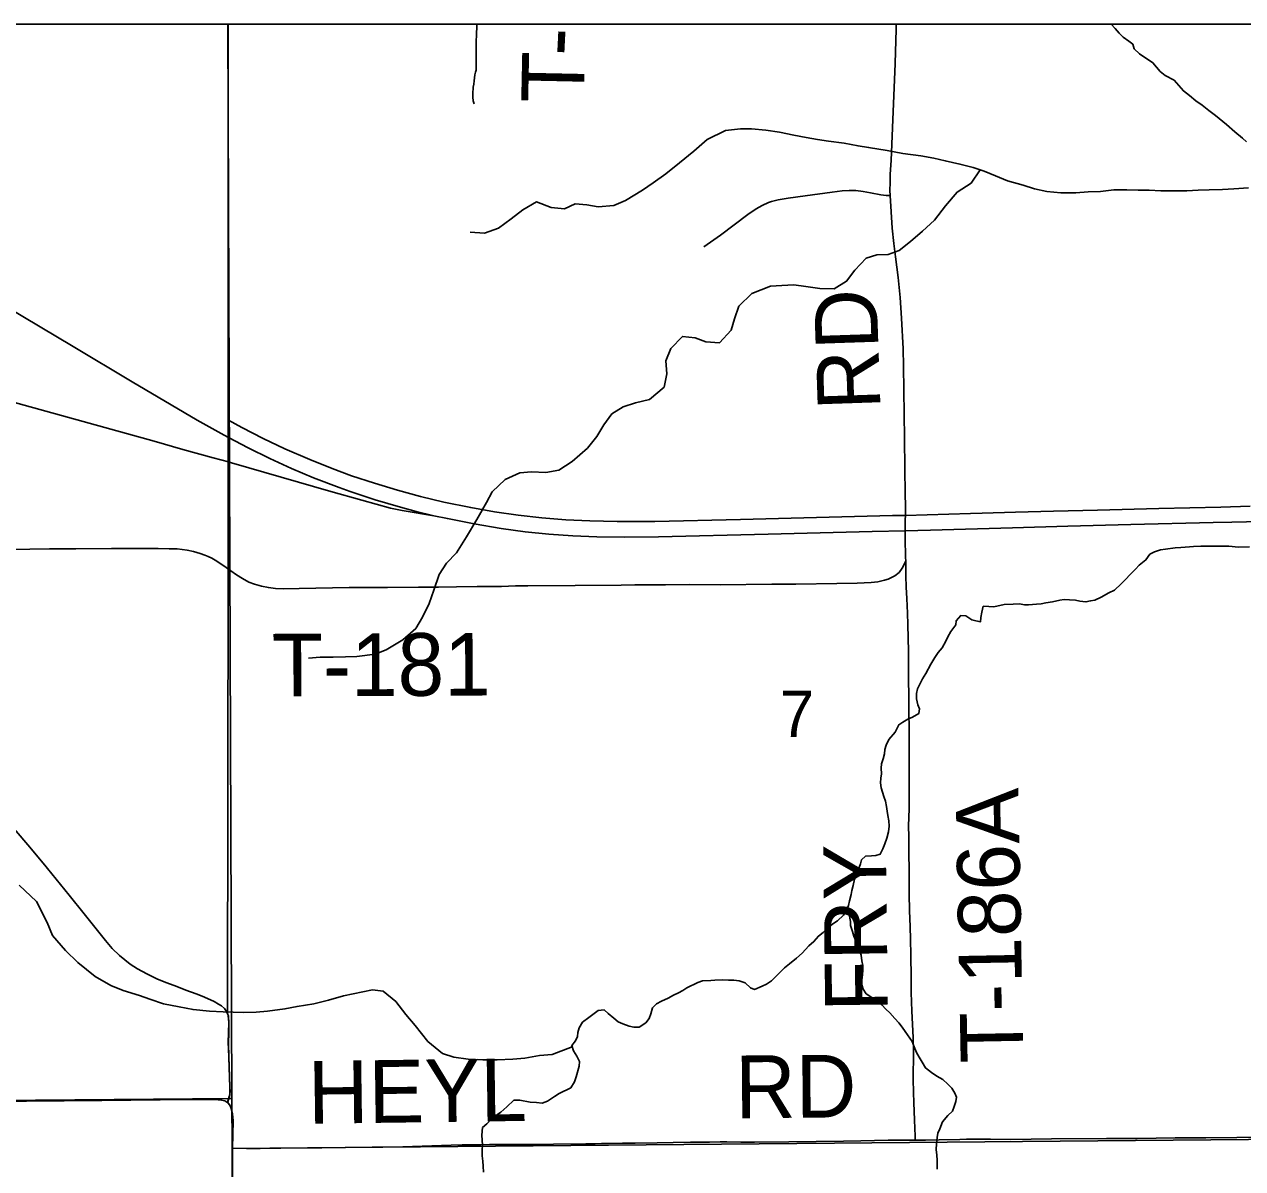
# Model space of a CAD drawing. Extents: x 0 to 34, y 0 to 22.
# Drawn here: x 5.466 to 6.57, y 19.863 to 20.9 of the extents above; entities that cross this region are included whole.
import ezdxf

# ---------------------------------------------------------------- set-up
doc = ezdxf.new("R2010")
doc.units = 0
for name, color, linetype in [('Default', 7, 'Continuous'), ('GM_X_County_Road', 7, 'Continuous'), ('GM_X_County_Road_Text', 7, 'Continuous'), ('GM_X_Minor_River', 7, 'Continuous'), ('GM_X_Section', 7, 'Continuous'), ('GM_X_Section_Text', 7, 'Continuous'), ('GM_X_State_Route', 7, 'Continuous'), ('GM_X_Township_Road', 7, 'Continuous'), ('GM_X_Township_Road_Text', 7, 'Continuous'), ('GM_X_US_Route', 7, 'Continuous'), ('SH_Data', 7, 'Continuous')]:
    doc.layers.add(name, color=color, linetype=linetype)

msp = doc.modelspace()

# ---------------------------------------------------------------- linework, layer by layer
at = {"layer": 'Default'}
for points in [[(5.6501, 20.9), (4.655, 20.9), (4.6576, 19.9182), (5.654, 19.9264)], [(6.763, 20.9), (5.6501, 20.9), (5.654, 19.9264), (5.6542, 19.8813), (6.7799, 19.8913)]]:
    msp.add_lwpolyline(points, close=True, dxfattribs=at)
at = {"layer": 'GM_X_County_Road'}
for points in [[(5.4211, 19.9239), (5.4677, 19.924), (5.536, 19.9247), (5.5889, 19.9253), (5.6323, 19.9256), (5.6416, 19.9254), (5.6446, 19.9251), (5.6474, 19.9243), (5.6501, 19.9226)], [(5.6501, 19.9226), (5.6517, 19.9208), (5.6531, 19.9183), (5.654, 19.9154), (5.6546, 19.9125), (5.655, 19.9064), (5.6546, 19.8814)], [(5.6546, 19.8814), (5.6671, 19.8812), (5.6795, 19.8811), (5.6982, 19.8814), (5.7353, 19.8818), (5.757, 19.8821), (5.7811, 19.8824), (5.8089, 19.8827), (5.8265, 19.8832), (5.8439, 19.8839), (5.8527, 19.8842), (5.8627, 19.8845), (5.8701, 19.8846), (5.8795, 19.8846), (5.8874, 19.8847), (5.9004, 19.8847), (5.9153, 19.8847), (5.9311, 19.8849), (5.9453, 19.885), (5.9746, 19.8854), (5.9832, 19.8856), (5.989, 19.8857), (5.9951, 19.8859), (6.0079, 19.8861), (6.0194, 19.8862), (6.0393, 19.8865), (6.0539, 19.8867), (6.0697, 19.8869), (6.0867, 19.8871), (6.0964, 19.8872), (6.1026, 19.8872), (6.1151, 19.8871), (6.1275, 19.8871), (6.1586, 19.8874), (6.1835, 19.8877), (6.2083, 19.888), (6.2238, 19.8883), (6.2486, 19.8887), (6.2732, 19.8889)], [(6.2732, 19.8889), (6.2826, 19.8889), (6.295, 19.8892), (6.3136, 19.8895), (6.3198, 19.8896), (6.3414, 19.8897), (6.3598, 19.8895), (6.3968, 19.89), (6.4465, 19.8902), (6.4745, 19.8904), (6.5087, 19.8908), (6.5273, 19.891), (6.5366, 19.891), (6.5646, 19.8913), (6.5894, 19.8916), (6.6204, 19.8917), (6.6452, 19.8916), (6.722, 19.892)]]:
    msp.add_lwpolyline(points, dxfattribs=at)
at = {"layer": 'GM_X_Minor_River'}
for points in [[(6.5736, 20.7934), (6.5698, 20.7967), (6.5628, 20.8027), (6.5555, 20.8091), (6.5455, 20.8173), (6.5394, 20.8218), (6.5332, 20.8266), (6.5275, 20.8307), (6.5217, 20.8356), (6.5163, 20.8397), (6.5078, 20.8495), (6.4998, 20.8535), (6.4952, 20.8573), (6.4886, 20.8652), (6.4764, 20.8734), (6.4717, 20.8778), (6.4705, 20.882), (6.4667, 20.8846), (6.4617, 20.8883), (6.4582, 20.8921), (6.4544, 20.8962), (6.4509, 20.9)], [(6.5752, 20.7519), (6.5619, 20.751), (6.5517, 20.7502), (6.5396, 20.7501), (6.5297, 20.7497), (6.5195, 20.7492), (6.4957, 20.749), (6.4854, 20.7497), (6.4752, 20.7496), (6.465, 20.7499), (6.4532, 20.7499), (6.4411, 20.7486), (6.4301, 20.7482), (6.4188, 20.7473), (6.4052, 20.7472), (6.3926, 20.7486), (6.3813, 20.7508), (6.371, 20.7542), (6.357, 20.7582), (6.346, 20.7627), (6.3357, 20.7668), (6.3258, 20.7701), (6.3137, 20.7734), (6.3004, 20.7764), (6.2902, 20.7786), (6.2784, 20.7808), (6.2621, 20.7829), (6.2477, 20.7855), (6.231, 20.7884), (6.2215, 20.7898), (6.2087, 20.7924), (6.1946, 20.7942), (6.1848, 20.7956), (6.1745, 20.7974), (6.1632, 20.7996), (6.1503, 20.8022), (6.1378, 20.804), (6.1249, 20.8054), (6.115, 20.8053), (6.1014, 20.8037), (6.0848, 20.7956), (6.0727, 20.7849), (6.0596, 20.7746), (6.0471, 20.7646), (6.0358, 20.7562), (6.026, 20.7497), (6.0106, 20.7404), (6, 20.7358), (5.986, 20.7346), (5.9757, 20.7364), (5.9651, 20.7374), (5.9553, 20.7328), (5.9432, 20.7339), (5.9299, 20.7391), (5.9175, 20.7318), (5.9069, 20.7237), (5.8956, 20.7153), (5.8828, 20.7107), (5.8699, 20.7117)], [(6.3321, 20.768), (6.324, 20.7561), (6.3112, 20.748), (6.3007, 20.7354), (6.2906, 20.7225), (6.2797, 20.7125), (6.2691, 20.7033), (6.2586, 20.6949), (6.2487, 20.6914), (6.2385, 20.691), (6.2287, 20.6882), (6.2185, 20.6772), (6.211, 20.6672), (6.1997, 20.6603), (6.1868, 20.6606), (6.174, 20.6624), (6.1633, 20.6639), (6.1524, 20.6634), (6.1421, 20.6626), (6.1251, 20.656), (6.1135, 20.6445), (6.1094, 20.6331), (6.1064, 20.6228), (6.0959, 20.6114), (6.0834, 20.6124), (6.0739, 20.6158), (6.0622, 20.6172), (6.0516, 20.6061), (6.0472, 20.5951), (6.048, 20.5833), (6.0458, 20.5712), (6.0323, 20.5601), (6.0198, 20.557), (6.0084, 20.5535), (5.9983, 20.5469), (5.9911, 20.537), (5.9848, 20.5264), (5.9761, 20.516), (5.9622, 20.5038), (5.9501, 20.4961), (5.9384, 20.4938), (5.9255, 20.4944), (5.9149, 20.4936), (5.9017, 20.4874), (5.8897, 20.4763), (5.8848, 20.4668), (5.8758, 20.4512), (5.8665, 20.4356), (5.8575, 20.4211), (5.8485, 20.4116), (5.8417, 20.4013), (5.8369, 20.3872), (5.8328, 20.375), (5.8268, 20.3628), (5.8205, 20.3526), (5.8088, 20.3422), (5.7937, 20.333), (5.7839, 20.3291), (5.7672, 20.3271), (5.757, 20.3267), (5.7457, 20.3266), (5.7339, 20.3265), (5.7233, 20.3257)], [(6.5761, 20.4265), (6.5662, 20.4263), (6.5575, 20.427), (6.5502, 20.4272), (6.532, 20.427), (6.5255, 20.4269), (6.5217, 20.4265), (6.5141, 20.426), (6.5088, 20.4256), (6.5001, 20.4243), (6.4955, 20.4239), (6.4902, 20.4219), (6.486, 20.4199)], [(6.486, 20.4199), (6.4823, 20.4146), (6.4763, 20.4099), (6.4729, 20.4061), (6.4684, 20.4018), (6.4635, 20.3965), (6.4598, 20.393), (6.4538, 20.3872), (6.4488, 20.3849), (6.4417, 20.381), (6.436, 20.3782), (6.4322, 20.3774), (6.428, 20.3766), (6.4223, 20.3773), (6.4185, 20.378), (6.4132, 20.3783), (6.4082, 20.3786), (6.4044, 20.3782), (6.3976, 20.3766), (6.3915, 20.3757), (6.3874, 20.3749), (6.3832, 20.3745), (6.376, 20.374), (6.3722, 20.374), (6.3676, 20.3747), (6.3619, 20.3746), (6.3539, 20.3741), (6.3444, 20.3721), (6.3399, 20.3724), (6.3349, 20.3727), (6.3335, 20.3674), (6.3328, 20.3624), (6.3324, 20.3586), (6.3282, 20.3593), (6.3244, 20.3604), (6.319, 20.3638), (6.3145, 20.3641), (6.3104, 20.3595), (6.31, 20.3557), (6.3055, 20.3499), (6.3029, 20.3449), (6.3011, 20.3411), (6.2977, 20.335), (6.294, 20.3308), (6.291, 20.3262), (6.2873, 20.32), (6.2828, 20.3116), (6.2799, 20.307), (6.2773, 20.302), (6.2754, 20.2978), (6.2743, 20.2937), (6.2744, 20.2887), (6.2756, 20.2834), (6.2772, 20.2796), (6.2765, 20.2754), (6.2708, 20.272), (6.2666, 20.2704), (6.2621, 20.2677), (6.2583, 20.2653), (6.255, 20.2584), (6.2494, 20.2519), (6.2468, 20.2466), (6.2457, 20.2427), (6.2454, 20.2389), (6.2443, 20.2344), (6.2428, 20.2298), (6.2425, 20.226), (6.2426, 20.2207), (6.2422, 20.2169), (6.2419, 20.2127), (6.2423, 20.2081), (6.2447, 20.2002), (6.2463, 20.196), (6.2471, 20.1911), (6.2479, 20.1869), (6.2484, 20.1831), (6.2492, 20.1782), (6.2496, 20.1733), (6.2489, 20.1683), (6.2475, 20.1626), (6.2457, 20.1573), (6.2438, 20.1527), (6.2416, 20.1481), (6.2374, 20.1469), (6.2336, 20.1465), (6.2283, 20.146), (6.2246, 20.1429), (6.2235, 20.1391), (6.2216, 20.1334), (6.2213, 20.1296), (6.2183, 20.1254), (6.2169, 20.1197), (6.2158, 20.1151), (6.2151, 20.1113), (6.2136, 20.1056), (6.2129, 20.1014), (6.2111, 20.0968), (6.2081, 20.0926), (6.2028, 20.0876), (6.1987, 20.0849), (6.1938, 20.081)], [(5.9624, 19.9733), (5.9443, 19.9663), (5.9326, 19.9654), (5.9194, 19.9631), (5.9084, 19.9622), (5.8944, 19.9617), (5.8815, 19.9616), (5.8682, 19.9623), (5.855, 19.9641), (5.8447, 19.9674), (5.8314, 19.9783), (5.8199, 19.9926), (5.8115, 20.0028), (5.8024, 20.0145), (5.7909, 20.0239), (5.7814, 20.025), (5.755, 20.0195), (5.7414, 20.0156), (5.7281, 20.0124), (5.713, 20.01), (5.702, 20.0077), (5.6861, 20.0057), (5.6759, 20.0048), (5.6642, 20.0044), (5.646, 20.005), (5.6335, 20.0056), (5.6187, 20.0071), (5.6062, 20.0096), (5.5918, 20.0122), (5.5796, 20.0166), (5.5702, 20.02), (5.5554, 20.0244), (5.5443, 20.0289), (5.5299, 20.0371), (5.5143, 20.0499), (5.5032, 20.0608), (5.4914, 20.0744), (5.4864, 20.0861), (5.4768, 20.105), (5.4611, 20.12)], [(6.2101, 20.0955), (6.2134, 20.0934), (6.2146, 20.087), (6.2147, 20.0832), (6.2163, 20.0779), (6.2175, 20.0737), (6.219, 20.0699), (6.2202, 20.0662), (6.223, 20.0605), (6.2242, 20.0563), (6.225, 20.0514), (6.2258, 20.0472), (6.2259, 20.0427), (6.2255, 20.0389), (6.2248, 20.0339), (6.2249, 20.0294), (6.2261, 20.0256), (6.2288, 20.0214), (6.2338, 20.0181), (6.2384, 20.0151), (6.243, 20.0114), (6.2465, 20.0076), (6.2503, 20.0043), (6.2549, 19.999), (6.2584, 19.9952), (6.2615, 19.9911), (6.2642, 19.9873), (6.2704, 19.9783), (6.2724, 19.9734), (6.2744, 19.9681), (6.2767, 19.964), (6.2794, 19.9594), (6.2825, 19.9542), (6.2879, 19.9501), (6.2929, 19.9467), (6.2983, 19.9437), (6.3029, 19.9396), (6.3064, 19.9359), (6.3091, 19.9313), (6.3106, 19.9276), (6.3099, 19.9238), (6.3085, 19.9192), (6.307, 19.915), (6.3029, 19.9111), (6.298, 19.9054), (6.2954, 19.8989), (6.2936, 19.8951), (6.2932, 19.8913), (6.2926, 19.8855), (6.2922, 19.8802), (6.2927, 19.8753), (6.2931, 19.8707), (6.2932, 19.8624)], [(6.1938, 20.081), (6.1897, 20.0771), (6.1855, 20.0737), (6.1814, 20.0687), (6.1769, 20.0648), (6.1709, 20.0583), (6.1656, 20.0536), (6.1592, 20.0486), (6.1547, 20.0451), (6.1468, 20.0371), (6.1431, 20.0332), (6.1385, 20.0301), (6.1344, 20.0282), (6.1276, 20.0254), (6.1238, 20.0269), (6.1191, 20.0314), (6.1138, 20.0332), (6.1088, 20.0339), (6.1039, 20.0338), (6.0982, 20.0341), (6.0917, 20.0337), (6.0879, 20.0336), (6.0803, 20.0331), (6.0762, 20.0316), (6.0663, 20.0269), (6.0626, 20.0245), (6.0588, 20.0222), (6.0542, 20.0203), (6.0493, 20.0175), (6.0433, 20.0148), (6.0388, 20.0124), (6.035, 20.0086), (6.0335, 20.0033), (6.0321, 19.9991), (6.0291, 19.9952), (6.0231, 19.9913), (6.0181, 19.9913), (6.0139, 19.992), (6.0082, 19.9942), (6.004, 19.996), (6.0001, 19.9994), (5.9951, 20.0035), (5.9913, 20.0069), (5.986, 20.0064), (5.9773, 19.9999), (5.9717, 19.9956), (5.9687, 19.9906), (5.9676, 19.9864), (5.9673, 19.9826), (5.9654, 19.9788), (5.962, 19.9746), (5.9636, 19.9697), (5.9667, 19.9648), (5.9691, 19.9602), (5.9687, 19.9557), (5.9658, 19.9461), (5.9644, 19.9416), (5.961, 19.9362), (5.9504, 19.9311), (5.9463, 19.9284), (5.9399, 19.9241), (5.935, 19.9222), (5.93, 19.9229), (5.9243, 19.9232), (5.9148, 19.9249), (5.9094, 19.9249), (5.903, 19.9191), (5.8978, 19.9141), (5.8895, 19.9083), (5.885, 19.9037), (5.8812, 19.9002), (5.8806, 19.8933), (5.8811, 19.8842), (5.8807, 19.88), (5.8808, 19.8747), (5.8813, 19.8698), (5.8817, 19.8652), (5.8821, 19.8599)]]:
    msp.add_lwpolyline(points, dxfattribs=at)
at = {"layer": 'GM_X_Section'}
for points in [[(4.6746, 18.9086), (5.6498, 18.8985), (5.6542, 19.8813), (5.654, 19.9264), (4.6576, 19.9182), (4.6526, 19.2311), (4.6746, 19.2311)], [(5.6542, 19.8813), (6.7799, 19.8913), (6.7847, 18.8752), (5.6499, 18.8708), (5.6498, 18.8985)]]:
    msp.add_lwpolyline(points, close=True, dxfattribs=at)
at = {"layer": 'GM_X_State_Route'}
for points in [[(5.6542, 19.8598), (5.6543, 19.8722), (5.6544, 19.8819), (5.6548, 19.9069), (5.6543, 19.913), (5.6538, 19.916), (5.6529, 19.9188), (5.6515, 19.9213), (5.6499, 19.9231), (5.6505, 19.9251), (5.6515, 19.9283), (5.652, 19.9308), (5.6521, 19.9336), (5.652, 19.9371), (5.6511, 19.9645), (5.6507, 19.9775), (5.651, 19.986), (5.6511, 19.9954), (5.6506, 20.0018), (5.6498, 20.0043), (5.6505, 20.4068), (5.6507, 20.5039), (5.6506, 20.5261), (5.6506, 20.5418), (5.6507, 20.9), (2.1, 20.9)], [(8.9, 20.9), (5.6507, 20.9), (5.6506, 20.5418), (5.6506, 20.5261), (5.6507, 20.5039), (5.6505, 20.4068), (5.6498, 20.0043), (5.6506, 20.0018), (5.6511, 19.9954), (5.651, 19.986), (5.6507, 19.9775), (5.6511, 19.9645), (5.652, 19.9371), (5.6521, 19.9336), (5.652, 19.9308), (5.6515, 19.9283), (5.6505, 19.9251), (5.6499, 19.9231), (5.6515, 19.9213), (5.6529, 19.9188), (5.6538, 19.916), (5.6543, 19.913), (5.6548, 19.9069), (5.6544, 19.8819), (5.6543, 19.8722), (5.6542, 19.8598)]]:
    msp.add_lwpolyline(points, dxfattribs=at)
at = {"layer": 'GM_X_Township_Road'}
for points in [[(5.8734, 20.8279), (5.8727, 20.8308), (5.8723, 20.8339), (5.8723, 20.8369), (5.8727, 20.843), (5.8732, 20.8458), (5.8735, 20.8488), (5.8738, 20.8516), (5.8742, 20.8543), (5.8746, 20.8567), (5.8753, 20.8585), (5.8754, 20.8613), (5.8753, 20.8673), (5.8752, 20.8765), (5.8752, 20.8796), (5.8753, 20.8858), (5.8756, 20.8889), (5.876, 20.9)], [(6.2505, 20.7449), (6.2503, 20.7495), (6.2504, 20.7567), (6.2506, 20.7642), (6.2513, 20.7767), (6.2527, 20.8061), (6.255, 20.8644), (6.2559, 20.8957), (6.256, 20.9)], [(6.0817, 20.6983), (6.0969, 20.7089), (6.1216, 20.7275), (6.1292, 20.7328), (6.1346, 20.7359), (6.1402, 20.7384), (6.1431, 20.7394), (6.1491, 20.741), (6.1582, 20.7426), (6.1735, 20.7446), (6.1979, 20.748), (6.2071, 20.7492), (6.2133, 20.7495), (6.2195, 20.7494), (6.226, 20.7486), (6.2326, 20.7473), (6.242, 20.7455), (6.2468, 20.7449), (6.2505, 20.7449)], [(6.2642, 20.441), (6.2642, 20.4509), (6.2643, 20.4548), (6.2645, 20.463), (6.2642, 20.4747), (6.2639, 20.4972), (6.2635, 20.5251), (6.2626, 20.5903), (6.2622, 20.6058), (6.2609, 20.6337), (6.2596, 20.6523), (6.2577, 20.6707), (6.2554, 20.6892), (6.2539, 20.7015), (6.2524, 20.7153), (6.2513, 20.7301), (6.2505, 20.7449)], [(6.2646, 20.4138), (6.2645, 20.4167), (6.2642, 20.4342), (6.2642, 20.441)], [(5.4002, 20.4244), (5.4061, 20.4244), (5.4243, 20.4243), (5.4426, 20.4241), (5.4708, 20.4244), (5.4885, 20.4246), (5.5086, 20.4247), (5.5125, 20.4247)], [(5.4843, 20.138), (5.4689, 20.1564), (5.4406, 20.1894), (5.416, 20.2175), (5.4102, 20.2247), (5.4067, 20.2299), (5.4052, 20.2326), (5.404, 20.2355), (5.403, 20.2384), (5.4023, 20.2414), (5.4014, 20.2476), (5.401, 20.2569), (5.4011, 20.2973), (5.4012, 20.3377), (5.4012, 20.3843), (5.4011, 20.4091), (5.4006, 20.4175), (5.4003, 20.4226), (5.4002, 20.4244)], [(5.5125, 20.4247), (5.5447, 20.4251), (5.5872, 20.4249), (5.5972, 20.4248), (5.6042, 20.4246), (5.6134, 20.4234), (5.619, 20.4223), (5.6251, 20.4205), (5.6295, 20.419), (5.6323, 20.4178), (5.6356, 20.4162), (5.6388, 20.4144), (5.6412, 20.4128), (5.6442, 20.4109), (5.6467, 20.4093), (5.6508, 20.4062)], [(5.6508, 20.4062), (5.6529, 20.4046), (5.658, 20.4011), (5.6634, 20.3978), (5.6692, 20.3946), (5.6745, 20.3927), (5.6808, 20.3907), (5.687, 20.3895), (5.6933, 20.3888), (5.701, 20.3885), (5.7149, 20.3886), (5.7603, 20.3895), (5.795, 20.3896), (5.8232, 20.3898), (5.8412, 20.39), (5.8575, 20.3903), (5.8762, 20.3905), (5.8983, 20.3906), (5.9109, 20.391), (5.9222, 20.391), (5.9651, 20.3913), (6.0068, 20.3917), (6.0191, 20.392), (6.0334, 20.392), (6.047, 20.3921), (6.0686, 20.3922), (6.0966, 20.3921), (6.1432, 20.3925), (6.1649, 20.3926), (6.2021, 20.3932), (6.2207, 20.3935), (6.2332, 20.3941), (6.2394, 20.3949), (6.2455, 20.3962), (6.2486, 20.3972), (6.2548, 20.4002), (6.2586, 20.4033), (6.2614, 20.407), (6.2631, 20.4106), (6.2646, 20.4138)], [(6.2732, 19.8889), (6.2731, 19.8923), (6.2725, 19.9068), (6.272, 19.9229), (6.2718, 19.9319), (6.2715, 19.944), (6.2718, 19.9681), (6.2714, 19.9817), (6.2702, 20.0058), (6.2697, 20.0227), (6.2697, 20.0363), (6.2694, 20.0564), (6.2689, 20.071), (6.2686, 20.082), (6.268, 20.0969), (6.2679, 20.1116), (6.2677, 20.1221), (6.2677, 20.1366), (6.2675, 20.1458), (6.2674, 20.1518), (6.2674, 20.164), (6.2672, 20.1732), (6.2677, 20.1893), (6.2679, 20.202), (6.2679, 20.2171), (6.2677, 20.2448), (6.2676, 20.2634), (6.2674, 20.2747), (6.2674, 20.2838), (6.2674, 20.2935), (6.2671, 20.3042), (6.2671, 20.3176), (6.267, 20.3316), (6.2665, 20.3561), (6.2662, 20.3665), (6.2656, 20.3797), (6.2651, 20.39), (6.2648, 20.4001), (6.2647, 20.4067), (6.2646, 20.4138)], [(5.65, 20.0037), (5.6484, 20.0062), (5.6472, 20.008), (5.6444, 20.0105), (5.6418, 20.0121), (5.6379, 20.0144), (5.6319, 20.0172), (5.627, 20.0194), (5.6216, 20.0213), (5.6121, 20.0247), (5.6041, 20.0281), (5.5951, 20.0314), (5.5864, 20.0348), (5.5768, 20.0394), (5.5685, 20.0439), (5.5618, 20.0483), (5.5568, 20.0521), (5.5521, 20.0561), (5.5455, 20.0626), (5.5393, 20.0696), (5.52, 20.0939), (5.5064, 20.1108), (5.4868, 20.1349), (5.4843, 20.138)], [(5.6501, 19.9226), (5.6507, 19.9246), (5.6518, 19.9278), (5.6522, 19.9302), (5.6523, 19.9331), (5.6522, 19.9366), (5.6513, 19.9639), (5.6509, 19.9769), (5.6512, 19.9855), (5.6513, 19.9949), (5.6508, 20.0013), (5.65, 20.0037)], [(5.6546, 19.8814), (5.655, 19.9064), (5.6546, 19.9125), (5.654, 19.9154), (5.6531, 19.9183), (5.6517, 19.9208), (5.6501, 19.9226)], [(5.6533, 19.4275), (5.6533, 19.4868), (5.6534, 19.5271), (5.6534, 19.5768), (5.6535, 19.6109), (5.6533, 19.6388), (5.6531, 19.6606), (5.6537, 19.7009), (5.6539, 19.7444), (5.6539, 19.7723), (5.654, 19.7941), (5.6541, 19.8096), (5.6542, 19.822), (5.6544, 19.8406), (5.6544, 19.8592), (5.6545, 19.8717), (5.6546, 19.8814)]]:
    msp.add_lwpolyline(points, dxfattribs=at)
at = {"layer": 'GM_X_US_Route'}
for points in [[(5.0186, 20.8668), (5.0195, 20.8666), (5.0237, 20.8653), (5.0343, 20.8619), (5.0461, 20.858), (5.0668, 20.8513), (5.0903, 20.843), (5.1106, 20.8352), (5.1307, 20.8267), (5.1505, 20.8177), (5.17, 20.8081), (5.1893, 20.7979), (5.2136, 20.7842), (5.2966, 20.7351), (5.3446, 20.7064), (5.5101, 20.6079), (5.5635, 20.576), (5.6224, 20.5414), (5.6468, 20.5277), (5.6508, 20.5255)], [(5.3661, 20.5825), (5.4798, 20.5508), (5.5835, 20.5221), (5.6094, 20.5148), (5.6369, 20.5072), (5.6509, 20.5034)], [(5.6508, 20.5413), (5.6629, 20.5346), (5.6823, 20.5247), (5.702, 20.5154), (5.7247, 20.5055), (5.7449, 20.4974), (5.7624, 20.4909), (5.7831, 20.4841), (5.8039, 20.4778), (5.8249, 20.4722), (5.846, 20.4671), (5.8704, 20.4621), (5.8918, 20.4583), (5.9133, 20.4552), (5.9349, 20.4527), (5.9566, 20.4509), (5.9783, 20.4499), (6.0031, 20.4494), (6.0373, 20.4495), (6.1148, 20.4511), (6.2525, 20.4548), (6.2643, 20.4548), (6.3234, 20.4568), (6.3339, 20.4571), (6.364, 20.4578), (6.3985, 20.4588), (6.4385, 20.4597), (6.494, 20.4611), (6.5502, 20.4624), (6.5767, 20.4633)], [(5.6508, 20.5255), (5.6687, 20.5161), (5.6882, 20.5065), (5.708, 20.4975), (5.728, 20.4891), (5.7512, 20.4802), (5.7612, 20.4766), (5.7838, 20.4692), (5.8068, 20.4623), (5.8208, 20.4586), (5.8368, 20.4546)], [(5.6509, 20.5034), (5.6535, 20.5027), (5.7437, 20.4767), (5.7717, 20.4688), (5.7977, 20.4616), (5.8084, 20.4595), (5.8368, 20.4546)], [(6.2642, 20.441), (6.2872, 20.4416), (6.3615, 20.4436), (6.4117, 20.4451), (6.4686, 20.4466), (6.5433, 20.4484), (6.5601, 20.4487), (6.613, 20.4499), (6.6781, 20.4517), (6.7565, 20.4537), (6.8054, 20.4545), (6.8675, 20.456), (7.0009, 20.4591), (7.0569, 20.4603), (7.2244, 20.4641), (7.3237, 20.4667), (7.4299, 20.47), (7.4542, 20.4705), (7.4873, 20.4717), (7.5438, 20.473), (7.5971, 20.4743), (7.6475, 20.4755)], [(5.8368, 20.4546), (5.8492, 20.4521), (5.8736, 20.4473), (5.8981, 20.4431), (5.9196, 20.4402), (5.9412, 20.438), (5.9629, 20.4364), (5.9846, 20.4354), (6.0095, 20.4351), (6.0406, 20.4354), (6.14, 20.4379), (6.2342, 20.4403), (6.2642, 20.441)]]:
    msp.add_lwpolyline(points, dxfattribs=at)
at = {"layer": 'SH_Data'}
msp.add_line((2.1, 20.9), (8.9, 20.9), dxfattribs=at)

# ---------------------------------------------------------------- texts
at = {"layer": 'GM_X_County_Road_Text'}
for s, rotation, p in [('RD', 0.4895, (6.1103, 19.9086)), ('HEYL', 0.7677, (5.7232, 19.9036))]:
    msp.add_text(s, height=0.05682, rotation=rotation, dxfattribs=at).set_placement(p)
at = {"layer": 'GM_X_Section_Text'}
msp.add_text('7', height=0.0419, rotation=0, dxfattribs=at).set_placement((6.1505, 20.2542))
at = {"layer": 'GM_X_Township_Road_Text'}
for s, height, rotation, p in [('-', 0.0568, 87.1848, (5.9738, 20.8704)), ('T', 0.0568, 88.7871, (5.9729, 20.8283)), ('RD', 0.05682, 91.9234, (6.2418, 20.5513)), ('T-181', 0.05682, 0.2855, (5.6902, 20.2908)), ('T-186A', 0.05682, 91.0706, (6.3713, 19.9592)), ('FRY', 0.05682, 90.7074, (6.2485, 20.0055))]:
    msp.add_text(s, height=height, rotation=rotation, dxfattribs=at).set_placement(p)

doc.saveas('drawing.dxf')
